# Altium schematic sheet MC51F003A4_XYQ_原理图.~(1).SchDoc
size A4
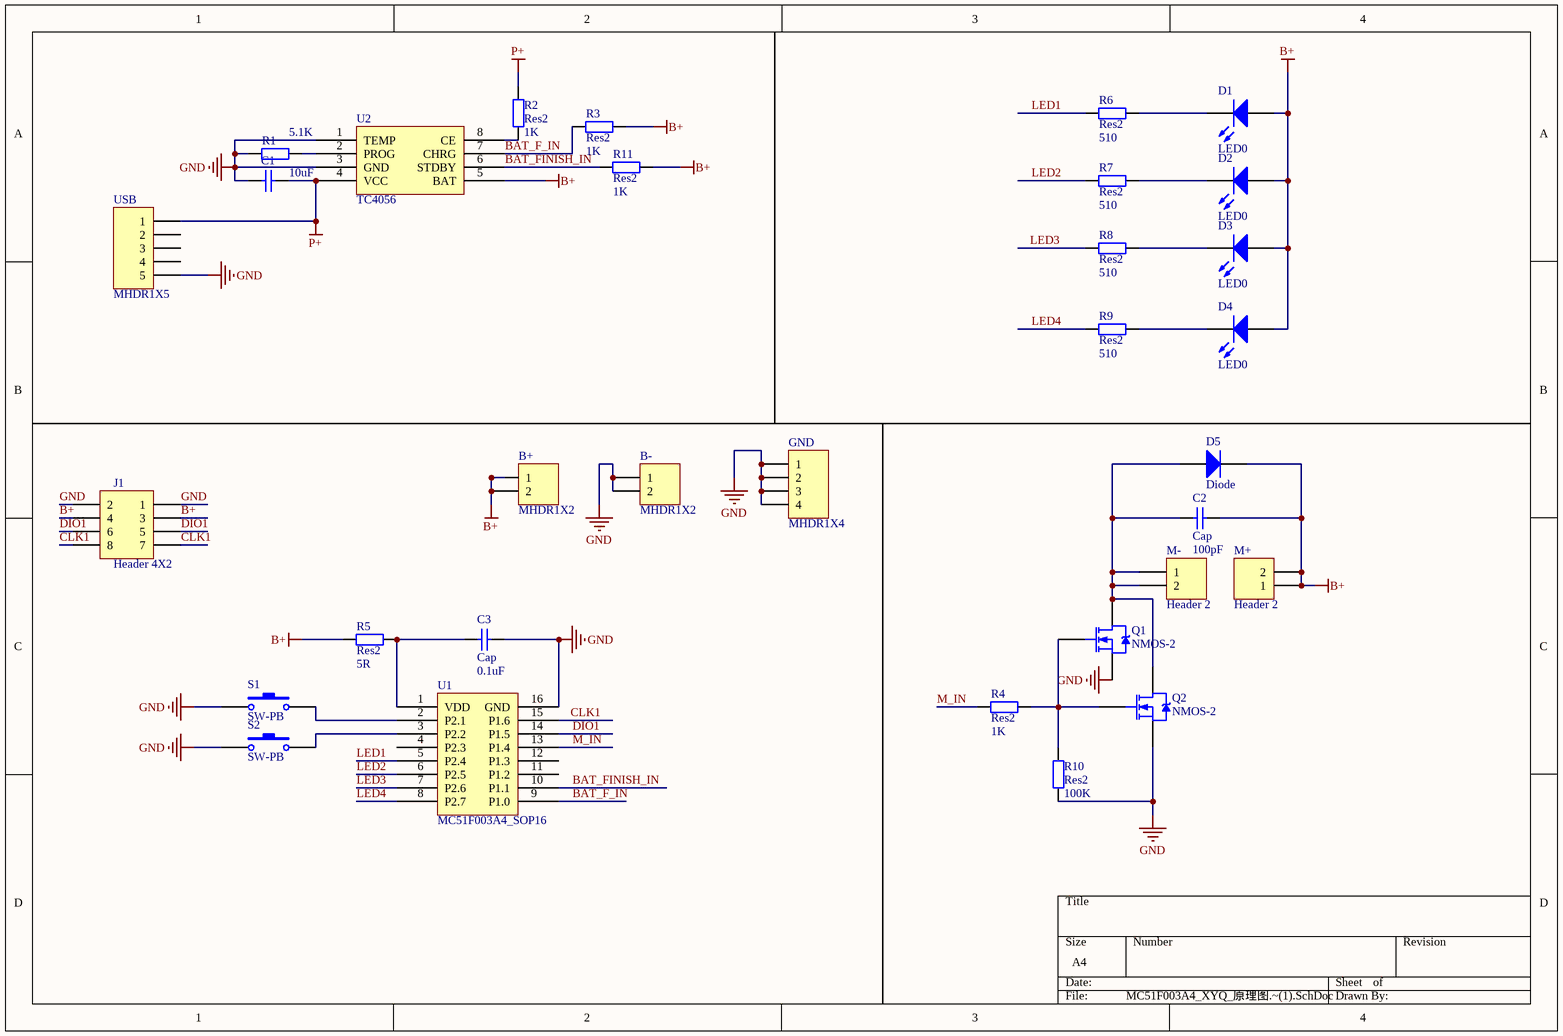
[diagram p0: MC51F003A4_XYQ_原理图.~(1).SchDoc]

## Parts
B+  MHDR1X2  [HDR1X2]
B-  MHDR1X2  [HDR1X2]
C1  value 10uF  [C0603]  (hidden comment: Cap)
C2  Cap  value 100pF  [C0603]
C3  Cap  value 0.1uF  [C0603]
D1  LED0  [LED0603-FD]
D2  LED0  [LED0603-FD]
D3  LED0  [LED0603-FD]
D4  LED0  [LED0603-FD]
D5  Diode  [SOD-123_L2.8-W1.8-LS3.7-RD]
GND  MHDR1X4  [HDR1X4]
J1  Header 4X2  [HDR2X4]
M+  Header 2  [HDR1X2]
M-  Header 2  [HDR1X2]
Q1  NMOS-2  [SOT-23-3_L2.9-W1.3-P1.90-LS2.4-BR]
Q2  NMOS-2  [SOT-23-3_L2.9-W1.3-P1.90-LS2.4-BR]
R1  value 5.1K  [R0603]  (hidden comment: Res2)
R2  Res2  value 1K  [R0603]
R3  Res2  value 1K  [R0603]
R4  Res2  value 1K  [R0603]
R5  Res2  value 5R  [R0603]
R6  Res2  value 510  [R0603]
R7  Res2  value 510  [R0603]
R8  Res2  value 510  [R0603]
R9  Res2  value 510  [R0603]
R10  Res2  value 100K  [R0603]
R11  Res2  value 1K  [R0603]
S1  SW-PB  [SW-SMD_4P-L6.0-W6.0-P4.50-LS10.0_UK-B0228XXX]
S2  SW-PB  [SW-SMD_4P-L6.0-W6.0-P4.50-LS10.0_UK-B0228XXX]
U1  MC51F003A4_SOP16  [SOP-16_L9.9-W3.9-P1.27-LS6.1-BL]
U2  TC4056  [SOP-8_L4.9-W3.9-P1.27-LS6.0-BL-EP]
USB  MHDR1X5  [MICRO-USB-SMD_MICRO-USB-A12]

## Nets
B+: B+.1 B+.2 C2.2 D1.1(A) D2.1(A) D3.1(A) D4.1(A) D5.2(K) J1.3 J1.4 M+.1 M+.2 R3.2 R5.1 R11.1 U2.5(BAT)
GND: B-.1 B-.2 C1.1 C3.2 GND.1 GND.2 GND.3 GND.4 J1.1 J1.2 Q1.3(S) Q2.3(S) R1.1 R10.1 S1.2 S2.2 U1.16(GND) U2.1(TEMP) U2.3(GND) USB.5
P+: C1.2 R2.2 U2.4(VCC) USB.1
BAT_F_IN: R3.1 U1.9(P1.0) U2.7(CHRG)
BAT_FINISH_IN: R11.2 U1.10(P1.1) U2.6(STDBY)
CLK1: J1.7 J1.8 U1.15(P1.6)
DIO1: J1.5 J1.6 U1.14(P1.5)
LED1: R6.2 U1.5(P2.4)
LED2: R7.2 U1.6(P2.5)
LED3: R8.2 U1.7(P2.6)
LED4: R9.1 U1.8(P2.7)
M_IN: R4.1 U1.13(P1.4)
NetC2_1: C2.1 D5.1(A) M-.1 M-.2 Q1.2(D) Q2.2(D)
NetC3_1: C3.1 R5.2 U1.1(VDD)
NetD1_2: D1.2(K) R6.1
NetD2_2: D2.2(K) R7.1
NetD3_2: D3.2(K) R8.1
NetD4_2: D4.2(K) R9.2
NetQ1_1: Q1.1(G) Q2.1(G) R4.2 R10.2
NetR1_2: R1.2 U2.2(PROG)
NetR2_1: R2.1 U2.8(CE)
NetS1_1: S1.1 U1.2(P2.1)
NetS2_1: S2.1 U1.3(P2.2)

Not connected (* = marked no-connect by the designer): U1 4(P2.3) 11(P1.2) 12(P1.3); USB 2 3 4

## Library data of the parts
B+ B- = MHDR1X2: Header, 2-Pin
C1-C3 = Cap: Capacitor
D1-D4 = LED0: Typical INFRARED GaAs LED
D5 = Diode: Default Diode
GND = MHDR1X4: Header, 4-Pin
J1 = Header 4X2: Header, 4-Pin, Dual row
M+ M- = Header 2: Header, 2-Pin
Q1 Q2 = NMOS-2: N-Channel Power MOSFET; Note: Pin 2 is electrically connected to pin 4.
R1-R11 = Res2: Resistor
S1 S2 = SW-PB: Switch
USB = MHDR1X5: Header, 5-Pin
